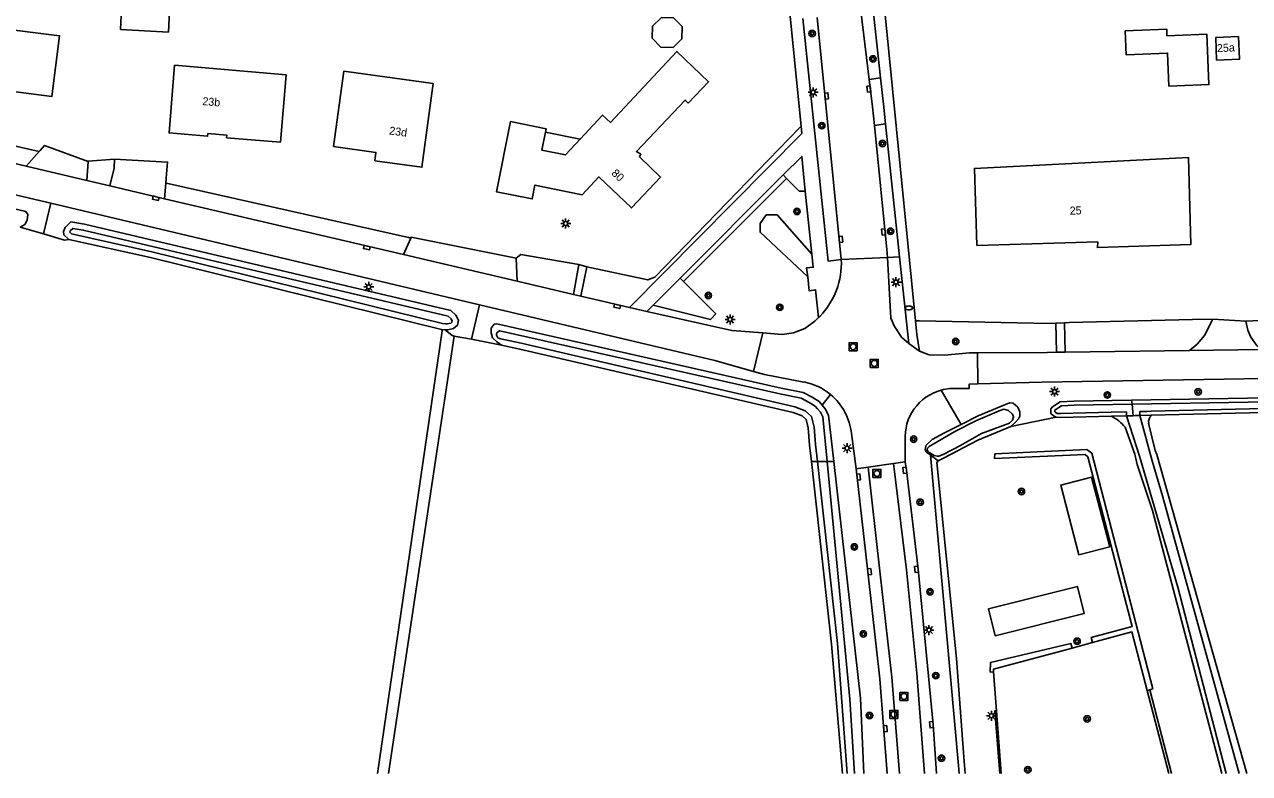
# Model space of a CAD drawing. Extents: x 140000 to 143000, y 403500 to 406000.
# Drawn here: x 140499.7 to 140652.7, y 403500 to 403593.5 of the extents above; entities that cross this region are included whole.
import ezdxf

# ---------------------------------------------------------------- set-up
doc = ezdxf.new("R2010")
doc.units = 0
for name, color, linetype in [('gg-afsc-erfafscheiding', 7, 'Continuous'), ('gg-afsc-hekwerk', 7, 'Continuous'), ('gg-anno-huisnummerreeks BGT', 7, 'Continuous'), ('gg-bbg-bijgebouw', 7, 'Continuous'), ('gg-bbg-hoofdgebouw', 7, 'Continuous'), ('gg-bbg-luifel en loopbrug', 7, 'Continuous'), ('gg-knt-bronhoudergrens', 7, 'Continuous'), ('gg-knt-onverhard', 7, 'Continuous'), ('gg-knt-verharding', 7, 'Continuous'), ('gg-knt-verharding nz', 7, 'Continuous'), ('gg-kntw-bovenkant insteek waterloop', 7, 'Continuous'), ('gg-kntw-waterlijn', 7, 'Continuous'), ('gt-grn-groengrens', 7, 'Continuous'), ('gt-grn-groengrens NZ', 7, 'Continuous'), ('gt-grn-vlakafsluiter', 7, 'Continuous'), ('gt-symb-boom', 7, 'Continuous'), ('gt-symb-brandkraan', 7, 'Continuous'), ('gt-symb-kolk', 7, 'Continuous'), ('gt-symb-lichtmast', 7, 'Continuous'), ('gt-symb-rioolschacht', 7, 'Continuous'), ('gx-grn-maaiveld', 7, 'Continuous')]:
    doc.layers.add(name, color=color, linetype=linetype)

# ---------------------------------------------------------------- blocks, each defined once
blk = doc.blocks.new('gt0-BOOM')
at = {"layer": 'gt-symb-boom'}
for radius in [0.4, 0.2]:
    blk.add_circle((0, 0), radius, dxfattribs=at)
blk = doc.blocks.new('gt0-LMAST')
at = {"layer": 'gt-symb-lichtmast'}
for p, q in [((-0.18, 0.17), (-0.45, 0.44)), ((-0.01, 0.25), (-0.01, 0.62)), ((0.17, 0.17), (0.44, 0.44)), ((-0.26, 0), (-0.63, 0)), ((-0.18, -0.18), (-0.45, -0.45)), ((-0.01, -0.25), (-0.01, -0.63)), ((0.44, -0.45), (0.17, -0.18)), ((0.24, 0), (0.62, 0))]:
    blk.add_line(p, q, dxfattribs=at)
blk.add_circle((-0.01, 0), 0.25, dxfattribs=at)
blk = doc.blocks.new('gt0-RS')
at = {"layer": 'gt-symb-rioolschacht'}
blk.add_lwpolyline([(-0.5, -0.5), (0.5, -0.5), (0.5, 0.5), (-0.5, 0.5)], close=True, dxfattribs=at)
blk.add_circle((0, 0), 0.375, dxfattribs=at)
blk = doc.blocks.new('gt0-KOLK')
at = {"layer": 'gt-symb-kolk'}
blk.add_lwpolyline([(0, 0), (0.38, 0), (0.38, 0.4), (-0.37, 0.4), (-0.37, 0), (0, 0)], dxfattribs=at)
blk = doc.blocks.new('gt0-BR')
at = {"layer": 'gt-symb-brandkraan'}
for centre, radius, start, end in [((-0.24, 0), 0.206, 107.5669, 252.4331), ((0.6, -2.66), 3, 106.892, 107.5669), ((0, -0.69), 0.938, 73.108, 106.892), ((-0.6, -2.66), 3, 72.4331, 73.108), ((0.24, 0), 0.206, 287.567, 72.4331), ((0.6, 2.66), 3, 252.4331, 253.108), ((0, 0.69), 0.938, 253.108, 286.8921), ((-0.6, 2.66), 3, 286.8921, 287.567)]:
    blk.add_arc(centre, radius, start, end, dxfattribs=at)

msp = doc.modelspace()

# ---------------------------------------------------------------- linework, layer by layer
at = {"layer": 'gg-afsc-erfafscheiding'}
for p, q in [((140607.14, 403595.14), (140611, 403556.5)), ((140654, 403556.56), (140652.25, 403556.48))]:
    msp.add_line(p, q, dxfattribs=at)
for points in [[(140501.53, 403577.66), (140486.94, 403580.93), (140486.06, 403581.18), (140478.93, 403582.72)], [(140596.7, 403580.82), (140596.5, 403580.62), (140578.43, 403561.96), (140577.55, 403561.62), (140569.93, 403563.25)], [(140510.94, 403576.7), (140507.64, 403576.47), (140507.64, 403576.4)], [(140547.94, 403566.83), (140547.65, 403566.91), (140517.6, 403573.66), (140517.35, 403573.72)], [(140561.11, 403564.33), (140561.7, 403564.79), (140568.92, 403563.57)], [(140611, 403556.5), (140611.5, 403556.5), (140627.82, 403556.19), (140628.53, 403556.22)], [(140648.12, 403556.71), (140645.6, 403556.68), (140630.2, 403556.29), (140629.61, 403556.26)]]:
    msp.add_lwpolyline(points, dxfattribs=at)
at = {"layer": 'gg-afsc-hekwerk'}
for p, q in [((140633.1, 403516.34), (140630.54, 403515.66)), ((140620.74, 403512.69), (140621.1, 403507.83)), ((140639.93, 403510.36), (140642.64, 403500)), ((140621.1, 403507.83), (140621.68, 403500))]:
    msp.add_line(p, q, dxfattribs=at)
for points in [[(140639.93, 403510.36), (140638.01, 403517.67), (140633.1, 403516.34)], [(140630.54, 403515.66), (140620.71, 403513.01), (140620.74, 403512.69)]]:
    msp.add_lwpolyline(points, dxfattribs=at)
at = {"layer": 'gg-bbg-bijgebouw'}
for points in [[(140518.17, 403603.14), (140512.18, 403603.47), (140511.7, 403592.9), (140517.68, 403592.56), (140518.04, 403600.38)], [(140578.11, 403591.79), (140579.18, 403590.68), (140580.71, 403590.66), (140581.81, 403591.72), (140581.83, 403593.25), (140580.77, 403594.36), (140579.24, 403594.38), (140578.14, 403593.32), (140578.11, 403591.79)], [(140637.19, 403592.74), (140637.3, 403589.75), (140642.48, 403589.95), (140642.64, 403585.83), (140647.63, 403586.02), (140647.39, 403592.3), (140642.4, 403592.11), (140642.37, 403592.93), (140637.19, 403592.74)]]:
    msp.add_lwpolyline(points, dxfattribs=at)
at = {"layer": 'gg-bbg-hoofdgebouw'}
for points in [[(140492.18, 403585.94), (140503.1, 403584.51), (140504.08, 403592.11), (140495.76, 403593.14)], [(140648.6, 403589.06), (140651.44, 403589.18), (140651.32, 403592.01), (140648.48, 403591.89), (140648.6, 403589.06)], [(140569.09, 403579.21), (140571.89, 403582.21), (140572.88, 403581.29), (140581.16, 403590.15), (140585.15, 403586.37), (140582.61, 403583.7), (140582.22, 403584.07), (140576.13, 403577.66), (140576.7, 403577.32), (140576.5, 403576.99), (140579.15, 403574.47), (140575.5, 403570.62), (140571.44, 403574.48), (140569.37, 403572.25), (140563.46, 403573.46), (140563.11, 403571.74), (140558.64, 403572.63), (140560.41, 403581.39), (140564.85, 403580.5), (140564.77, 403580.09)], [(140532.37, 403587.25), (140518.45, 403588.43), (140517.76, 403579.98), (140522.56, 403579.57), (140522.59, 403579.89), (140524.97, 403579.69), (140524.94, 403579.38), (140531.66, 403578.81), (140532.37, 403587.25)], [(140538.31, 403578.27), (140543.6, 403577.55), (140543.46, 403576.51), (140549.33, 403575.7), (140550.76, 403586.14), (140539.6, 403587.67), (140538.31, 403578.27)], [(140569.09, 403579.21), (140567.25, 403577.24), (140564.31, 403577.83), (140564.77, 403580.09)], [(140618.66, 403565.91), (140633.75, 403566.37), (140633.7, 403565.66), (140645.36, 403566.04), (140645.07, 403576.92), (140618.35, 403575.55), (140618.66, 403565.91)]]:
    msp.add_lwpolyline(points, dxfattribs=at)
at = {"layer": 'gg-bbg-luifel en loopbrug'}
msp.add_line((140569.09, 403579.21), (140564.77, 403580.09), dxfattribs=at)
at = {"layer": 'gg-knt-bronhoudergrens'}
for p, q in [((140502.08, 403567.36), (140499.15, 403568.2)), ((140553.37, 403554.62), (140555.51, 403554.21)), ((140555.51, 403554.21), (140559.28, 403553.49))]:
    msp.add_line(p, q, dxfattribs=at)
msp.add_lwpolyline([(140502.08, 403567.36), (140504.7, 403566.61), (140505.22, 403566.68)], dxfattribs=at)
at = {"layer": 'gg-knt-onverhard'}
for points in [[(140631.37, 403527.31), (140635.24, 403528.29), (140632.98, 403537), (140629.12, 403536.02), (140631.37, 403527.31)], [(140620.93, 403517.17), (140620.09, 403520.55), (140631.21, 403523.36), (140632.05, 403519.97), (140620.93, 403517.17)]]:
    msp.add_lwpolyline(points, dxfattribs=at)
at = {"layer": 'gg-knt-verharding'}
for p, q in [((140601.72, 403564.17), (140598.71, 403594.39)), ((140606.62, 403586.84), (140605.22, 403586.66)), ((140499.92, 403575.82), (140479.44, 403580.61)), ((140607.24, 403581.1), (140605.87, 403580.92)), ((140607.24, 403581.1), (140608.99, 403564.52)), ((140499.92, 403575.82), (140501.53, 403577.66)), ((140480.99, 403576.41), (140502.99, 403571.2)), ((140507.5, 403574.04), (140507.64, 403576.4)), ((140510.37, 403573.37), (140507.5, 403574.04)), ((140517.19, 403571.77), (140517.35, 403573.72)), ((140581.58, 403561.83), (140594.45, 403574.73)), ((140597.22, 403572.72), (140598.04, 403564.86)), ((140502.99, 403571.2), (140556.53, 403558.53)), ((140547.05, 403564.78), (140517.19, 403571.77)), ((140547.05, 403564.78), (140547.94, 403566.83)), ((140608.99, 403564.52), (140607.47, 403564.43)), ((140608.99, 403564.52), (140610.14, 403553.67)), ((140561.23, 403561.46), (140561.11, 403564.33)), ((140568.28, 403559.81), (140568.92, 403563.57)), ((140569.93, 403563.25), (140568.92, 403563.57)), ((140569.18, 403559.6), (140569.93, 403563.25)), ((140601.72, 403564.17), (140607.47, 403564.43)), ((140568.28, 403559.81), (140561.23, 403561.46)), ((140578.24, 403558.49), (140581.58, 403561.83)), ((140569.18, 403559.6), (140568.28, 403559.81)), ((140575.27, 403558.17), (140569.18, 403559.6)), ((140577.42, 403557.67), (140578.24, 403558.49)), ((140577.42, 403557.67), (140575.27, 403558.17)), ((140598.87, 403556.93), (140599.06, 403557.11)), ((140628.53, 403556.22), (140629.61, 403556.26)), ((140628.58, 403552.59), (140628.53, 403556.22)), ((140629.68, 403552.6), (140629.61, 403556.26)), ((140648.12, 403556.71), (140652.25, 403556.48)), ((140590.74, 403550.21), (140591.9, 403555.02)), ((140610.14, 403553.67), (140611.47, 403552.75)), ((140618.75, 403552.54), (140618.76, 403548.65)), ((140629.68, 403552.6), (140628.58, 403552.59)), ((140645.2, 403552.8), (140629.68, 403552.6)), ((140603.58, 403538.02), (140602.99, 403542.43)), ((140609.7, 403538.91), (140609.7, 403541.54)), ((140608.24, 403538.7), (140605.06, 403538.24)), ((140609.7, 403538.91), (140608.24, 403538.7)), ((140605.06, 403538.24), (140603.58, 403538.02))]:
    msp.add_line(p, q, dxfattribs=at)
for points in [[(140586.17, 403687.39), (140589.45, 403654.67), (140591.51, 403632.7), (140593.79, 403609.93), (140596.7, 403580.82)], [(140605.22, 403586.66), (140601.49, 403617.19), (140601.48, 403617.28)], [(140603.32, 403617.43), (140603.34, 403617.27), (140606.62, 403586.84)], [(140601.72, 403564.17), (140600.09, 403563.95), (140596.92, 403594.26)], [(140606.62, 403586.84), (140606.98, 403583.55), (140607.24, 403581.1)], [(140575.27, 403558.17), (140596.79, 403579.92), (140596.7, 403580.82)], [(140607.47, 403564.43), (140607.41, 403565.43), (140605.87, 403580.92)], [(140507.64, 403576.4), (140502.21, 403578.43), (140501.64, 403577.78), (140501.53, 403577.66)], [(140594.45, 403574.73), (140596.77, 403577.05), (140597.22, 403572.72)], [(140510.37, 403573.37), (140510.89, 403575.58), (140510.94, 403576.7)], [(140510.94, 403576.7), (140517.56, 403576.34), (140517.4, 403574.32), (140517.35, 403573.72)], [(140561.11, 403564.33), (140547.99, 403566.95), (140547.94, 403566.83)], [(140598.04, 403564.86), (140598.22, 403563.21), (140597.39, 403563.14), (140597.52, 403562.01)], [(140610.14, 403553.67), (140609.25, 403554.48), (140608.35, 403555.8), (140607.92, 403556.85), (140607.47, 403564.43)], [(140597.52, 403562.01), (140597.71, 403560.26), (140598.51, 403560.4), (140598.87, 403556.93)], [(140556.53, 403558.53), (140585.93, 403551.57), (140590.74, 403550.21)], [(140591.9, 403555.02), (140588.03, 403555.33), (140577.42, 403557.67)], [(140591.9, 403555.02), (140594.35, 403554.83), (140595.75, 403555.01), (140597.17, 403555.58), (140598.41, 403556.48), (140598.87, 403556.93)], [(140611.47, 403552.75), (140611.17, 403554.81), (140611, 403556.5)], [(140645.2, 403552.8), (140646.16, 403553.61), (140647.08, 403554.68), (140648.12, 403556.71)], [(140654.26, 403552.92), (140653.6, 403553.5), (140652.89, 403554.47), (140652.51, 403555.37), (140652.25, 403556.48)], [(140611.47, 403552.75), (140612.7, 403552.28), (140614.62, 403552.23), (140617.72, 403552.53), (140618.75, 403552.54)], [(140628.58, 403552.59), (140627.45, 403552.57), (140618.75, 403552.54)], [(140590.74, 403550.21), (140592.12, 403549.82), (140597.05, 403548.88)], [(140618.76, 403548.65), (140626.77, 403548.88), (140682.38, 403549.77), (140697.19, 403549.94), (140721.66, 403550.45)], [(140618.76, 403548.65), (140617.69, 403548.62), (140617.71, 403548.08), (140616.3, 403548.06)], [(140609.7, 403538.91), (140609.85, 403537.88), (140611.31, 403525.5), (140613.18, 403506.1), (140613.63, 403500)], [(140603.58, 403538.02), (140605.05, 403525.18), (140606.53, 403511.82), (140607.46, 403500)]]:
    msp.add_lwpolyline(points, dxfattribs=at)
for centre, radius, start, end in [((140592.2, 403563.72), 9.53, 316.0882, 2.7018), ((140595.69, 403541.67), 7.34, 50.3236, 79.3091), ((140615.8, 403541.97), 6.11, 105.08, 184.0606), ((140615.8, 403541.96), 6.12, 85.3219, 105.067), ((140595.69, 403541.67), 7.34, 5.9567, 50.3269)]:
    msp.add_arc(centre, radius, start, end, dxfattribs=at)
at = {"layer": 'gg-knt-verharding nz'}
for p, q in [((140507.5, 403574.04), (140499.92, 403575.82)), ((140517.19, 403571.77), (140510.37, 403573.37)), ((140561.23, 403561.46), (140547.05, 403564.78)), ((140654.26, 403552.92), (140645.2, 403552.8))]:
    msp.add_line(p, q, dxfattribs=at)
for points in [[(140605.87, 403580.92), (140605.63, 403583.24), (140605.22, 403586.66)], [(140608.24, 403538.7), (140609.86, 403525.41), (140611.14, 403512.54), (140612.11, 403500)], [(140605.06, 403538.24), (140606.54, 403525.25), (140608.01, 403512.01), (140608.98, 403500)]]:
    msp.add_lwpolyline(points, dxfattribs=at)
at = {"layer": 'gg-kntw-bovenkant insteek waterloop'}
for p, q in [((140545.18, 403500), (140553.37, 403554.62)), ((140640.44, 403544.68), (140640.44, 403544.73)), ((140617.08, 403501.48), (140617.19, 403500))]:
    msp.add_line(p, q, dxfattribs=at)
for points in [[(140483.59, 403571.74), (140483.14, 403572.17), (140482.95, 403572.67), (140483.05, 403573.09), (140483.45, 403573.62), (140484.16, 403573.8), (140484.88, 403573.71), (140499.85, 403570.17), (140500.13, 403569.78), (140500.02, 403569.09), (140499.73, 403568.54), (140499.15, 403568.2)], [(140552.23, 403555.4), (140552.57, 403555.38), (140553.27, 403555.55), (140553.77, 403555.96), (140553.89, 403556.6), (140553.58, 403557.22), (140552.96, 403557.79), (140507.18, 403568.58), (140505.48, 403568.86), (140504.77, 403568.17), (140504.58, 403567.67), (140504.6, 403567.25), (140505.22, 403566.68)], [(140551.8, 403555.42), (140515.42, 403564.42), (140505.22, 403566.68)], [(140551.8, 403555.42), (140551.86, 403555.26), (140543.8, 403500)], [(140552.23, 403555.4), (140553.1, 403554.67), (140553.37, 403554.62)], [(140599.33, 403546), (140598.95, 403546.46), (140598.08, 403546.98), (140596.94, 403547.57), (140594.21, 403548.12), (140558.68, 403556.14), (140558.37, 403556.09), (140558, 403555.62), (140557.99, 403555.02), (140558.15, 403554.4), (140558.7, 403553.89), (140559.28, 403553.49)], [(140559.28, 403553.49), (140561.58, 403552.99), (140595.7, 403545.06), (140596.81, 403544.65), (140597.32, 403544.18), (140597.57, 403543.14), (140597.76, 403541), (140597.99, 403538.96)], [(140637.98, 403546.6), (140669.4, 403547.14), (140701.92, 403547.95), (140724.06, 403548.17), (140726.4, 403548.1), (140728.88, 403548.15), (140731, 403547.96), (140732.62, 403547.58), (140735.03, 403546.68), (140739.62, 403544.8), (140744.58, 403542.18), (140751.39, 403537.28), (140756.59, 403533.19), (140762.93, 403527.96), (140764.95, 403526.17), (140765.01, 403525.73), (140764.89, 403525.42), (140764.49, 403525.17), (140764.09, 403525.01)], [(140622.89, 403543.34), (140623.38, 403543.8), (140623.84, 403544.3), (140624.03, 403544.61), (140624.02, 403545.17), (140623.76, 403545.74), (140623.18, 403546.24), (140622.74, 403546.3), (140618.82, 403544.67), (140616.67, 403543.58)], [(140637.98, 403546.6), (140630.78, 403546.47), (140629.07, 403546.39), (140628.08, 403545.77), (140627.91, 403545.54), (140627.9, 403544.93), (140628.22, 403544.67), (140628.55, 403544.47)], [(140764.09, 403525.01), (140763.67, 403525.16), (140760.49, 403527.81), (140748.98, 403536.24), (140744.85, 403539.39), (140741.38, 403541.62), (140739.5, 403542.55), (140737.38, 403543.46), (140735.14, 403544.28), (140732.82, 403545.03), (140729.77, 403545.62), (140726.17, 403546.12), (140723.11, 403546.38), (140716.17, 403546.24), (140699.29, 403546.03), (140666.78, 403545.36), (140640.44, 403544.73)], [(140599.33, 403546), (140599.72, 403545.54), (140600.14, 403544.75), (140600.79, 403538.96)], [(140612.87, 403539.75), (140612.75, 403539.87), (140612.44, 403540.03), (140612.26, 403540.19), (140612.2, 403540.51), (140612.33, 403540.98), (140613.07, 403541.7), (140614.52, 403542.49), (140616.67, 403543.58)], [(140613.83, 403539.04), (140614.49, 403539.38), (140618.76, 403541.62), (140622.89, 403543.34)], [(140628.55, 403544.47), (140629.09, 403544.45), (140635.45, 403544.61)], [(140637.17, 403543.25), (140638.4, 403539.85), (140638.66, 403538.6), (140640.58, 403532.85), (140649.24, 403500)], [(140640.11, 403543.72), (140640.94, 403540.34), (140641.14, 403539.82), (140652.36, 403500)], [(140597.99, 403538.96), (140600.48, 403516.15), (140601.85, 403500)], [(140600.79, 403538.96), (140604.12, 403509.42), (140604.54, 403500)], [(140612.87, 403539.75), (140616.36, 403501), (140616.43, 403500)], [(140617.08, 403501.48), (140616.1, 403514.37), (140613.67, 403538.85), (140613.83, 403539.04)]]:
    msp.add_lwpolyline(points, dxfattribs=at)
for centre, radius, start, end in [((140641.17, 403543.89), 1.07, 132.4125, 189.1557), ((140633.11, 403539.89), 5.26, 39.6282, 63.6249)]:
    msp.add_arc(centre, radius, start, end, dxfattribs=at)
at = {"layer": 'gg-kntw-waterlijn'}
msp.add_line((140552.23, 403555.4), (140551.8, 403555.42), dxfattribs=at)
for points in [[(140552.93, 403556.24), (140553.09, 403556.37), (140553.11, 403556.49), (140552.97, 403556.76), (140552.6, 403557.1), (140507.03, 403567.84), (140505.73, 403568.06), (140505.41, 403567.75), (140505.35, 403567.58), (140505.58, 403567.36), (140515.59, 403565.15), (140551.91, 403556.17), (140552.27, 403556.15), (140552.5, 403556.14), (140552.93, 403556.24)], [(140598.74, 403538.96), (140598.51, 403541.08), (140598.31, 403543.26), (140597.99, 403544.58), (140597.21, 403545.3), (140595.92, 403545.78), (140561.74, 403553.72), (140559, 403554.32)], [(140599.94, 403538.96), (140599.41, 403544.52), (140599.1, 403545.12), (140598.76, 403545.51), (140598.45, 403545.88), (140597.72, 403546.33), (140596.69, 403546.85), (140594.05, 403547.39), (140559.24, 403555.24)], [(140638.03, 403546.1), (140669.41, 403546.64)], [(140613.91, 403539.64), (140614.44, 403539.82), (140616.6, 403540.96), (140619.23, 403542.43), (140622.72, 403543.76), (140623.1, 403544.1), (140623.23, 403544.53), (140623.1, 403544.88), (140622.62, 403545.32), (140622.02, 403545.48), (140621.45, 403545.29), (140618.52, 403544.03), (140615.92, 403542.7), (140612.71, 403540.82), (140612.5, 403540.62), (140612.44, 403540.35), (140612.55, 403540.15), (140613.3, 403539.71), (140613.71, 403539.62), (140613.91, 403539.64)], [(140638.03, 403546.1), (140630.8, 403545.97), (140629.23, 403545.89), (140628.42, 403545.39), (140628.41, 403545.37), (140628.4, 403545.16), (140628.51, 403545.08), (140628.7, 403544.96), (140629.09, 403544.95), (140635.44, 403545.11), (140637.33, 403545.15), (140637.34, 403544.65)], [(140637.34, 403544.65), (140639.01, 403539.49), (140643.74, 403523.25), (140649.81, 403500)], [(140666.77, 403545.86), (140640.43, 403545.23), (140639.9, 403545.21), (140638.99, 403545.19), (140639, 403544.69)], [(140639, 403544.69), (140640.54, 403539.02), (140641.84, 403534.65), (140651.43, 403500)], [(140598.74, 403538.96), (140601.23, 403516.23), (140602.47, 403500)], [(140599.94, 403538.96), (140602.79, 403509.29), (140603.38, 403500)], [(140613.83, 403539.04), (140613.33, 403539.41), (140612.87, 403539.75)]]:
    msp.add_lwpolyline(points, dxfattribs=at)
msp.add_arc((140559.13, 403554.78), 0.475, 75.6411, 254.8534, dxfattribs=at)
at = {"layer": 'gt-grn-groengrens'}
for p, q in [((140582, 403561.41), (140594.87, 403574.3)), ((140594.45, 403574.73), (140594.87, 403574.3)), ((140581.58, 403561.83), (140582, 403561.41)), ((140640.27, 403510.46), (140639.93, 403510.36)), ((140640.27, 403510.46), (140642.96, 403500))]:
    msp.add_line(p, q, dxfattribs=at)
for points in [[(140597.22, 403572.72), (140596.46, 403572.72), (140594.87, 403574.3)], [(140598.04, 403564.86), (140593.7, 403569.74), (140592.34, 403569.74), (140591.57, 403568.68), (140591.57, 403567.58), (140597.52, 403562.01)], [(140578.24, 403558.49), (140585.37, 403556.67), (140586.03, 403557.38), (140582, 403561.41)], [(140632.53, 403539.54), (140632.17, 403539.83), (140620.85, 403539.33), (140620.91, 403539.91), (140632.4, 403540.45), (140633.03, 403540)], [(140632.53, 403539.54), (140638.07, 403518.34), (140632.93, 403516.99), (140633.1, 403516.34)], [(140633.03, 403540), (140640.63, 403510.59), (140640.27, 403510.46)], [(140630.54, 403515.66), (140630.38, 403516.25), (140620.34, 403513.85), (140620.33, 403512.66), (140620.74, 403512.69)], [(140621.1, 403507.83), (140620.88, 403507.81), (140621.53, 403500)]]:
    msp.add_lwpolyline(points, dxfattribs=at)
at = {"layer": 'gt-grn-groengrens NZ'}
for p, q in [((140502.99, 403571.2), (140502.08, 403567.36)), ((140556.53, 403558.53), (140555.51, 403554.21)), ((140616.67, 403543.58), (140614.21, 403547.87)), ((140600.38, 403547.32), (140599.33, 403546)), ((140622.89, 403543.34), (140628.55, 403544.47))]:
    msp.add_line(p, q, dxfattribs=at)
at = {"layer": 'gt-grn-vlakafsluiter'}
for p, q in [((140637.34, 403544.65), (140635.45, 403544.61)), ((140639, 403544.69), (140640.44, 403544.73)), ((140598.74, 403538.96), (140597.99, 403538.96)), ((140599.94, 403538.96), (140598.74, 403538.96)), ((140599.94, 403538.96), (140600.79, 403538.96))]:
    msp.add_line(p, q, dxfattribs=at)
at = {"layer": 'gx-grn-maaiveld'}
for p, q in [((140638.03, 403546.1), (140637.98, 403546.6)), ((140637.34, 403544.65), (140638.18, 403544.67)), ((140638.03, 403546.1), (140638.18, 403544.67))]:
    msp.add_line(p, q, dxfattribs=at)
msp.add_lwpolyline([(140638.18, 403544.67), (140638.41, 403544.68), (140639, 403544.69)], dxfattribs=at)

# ---------------------------------------------------------------- block references
at = {"layer": 'gt-symb-boom'}
for p in [(140598.08, 403592.4), (140605.67, 403589.22), (140599.28, 403580.89), (140606.86, 403578.66), (140596.18, 403570.18), (140607.87, 403567.7), (140585.11, 403559.68), (140594.03, 403558.2), (140616.01, 403553.94), (140646.29, 403547.65), (140634.95, 403547.26), (140610.76, 403541.74), (140624.22, 403535.21), (140611.57, 403533.87), (140603.35, 403528.29), (140612.8, 403522.69), (140604.47, 403517.43), (140631.17, 403516.51), (140613.52, 403512.22), (140605.24, 403507.23), (140632.43, 403506.82), (140614.23, 403501.9), (140625.02, 403500.47)]:
    msp.add_blockref('gt0-BOOM', p, dxfattribs=at)
at = {"layer": 'gt-symb-brandkraan'}
msp.add_blockref('gt0-BR', (140610.15, 403558.13), dxfattribs=at)
at = {"layer": 'gt-symb-kolk'}
for p, rotation in [((140599.68, 403584.59), -84.31751152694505), ((140605.36, 403585.48), 96.96487483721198), ((140516.14, 403572.02), 166.81908759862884), ((140607.19, 403567.63), 95.69051865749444), ((140601.47, 403566.68), -84.31751152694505), ((140542.5, 403565.85), 166.8190875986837), ((140573.77, 403558.53), 166.81908759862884), ((140603.69, 403537), -83.4815727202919), ((140609.85, 403537.88), 97.29919145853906), ((140605.05, 403525.18), -83.66069936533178), ((140611.31, 403525.5), 96.19315871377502), ((140613.18, 403506.1), 94.69394290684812), ((140607.02, 403505.58), -85.50040773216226)]:
    msp.add_blockref('gt0-KOLK', p, dxfattribs=dict(at, rotation=rotation))
at = {"layer": 'gt-symb-lichtmast'}
for p in [(140598.21, 403585.05), (140567.3, 403568.67), (140608.56, 403561.35), (140542.7, 403560.75), (140587.83, 403556.69), (140628.36, 403547.68), (140602.45, 403540.62), (140612.67, 403517.91), (140620.48, 403507.21)]:
    msp.add_blockref('gt0-LMAST', p, dxfattribs=at)
at = {"layer": 'gt-symb-rioolschacht'}
for p in [(140603.2, 403553.29), (140605.84, 403551.2), (140606.17, 403537.46), (140609.54, 403509.63), (140608.3, 403507.38)]:
    msp.add_blockref('gt0-RS', p, dxfattribs=at)

# ---------------------------------------------------------------- texts
at = {"layer": 'gg-anno-huisnummerreeks BGT'}
for s, rotation, p in [('25a', 2.5, (140648.66, 403590.06)), ('23b', 355.2, (140521.88, 403583.46)), ('23d', 352.2, (140545.2, 403579.8)), ('80', 316.6, (140572.93, 403574.85)), ('25', 1.7, (140630.26, 403569.77))]:
    msp.add_text(s, height=1, rotation=rotation, dxfattribs=at).set_placement(p)

doc.saveas('drawing.dxf')
